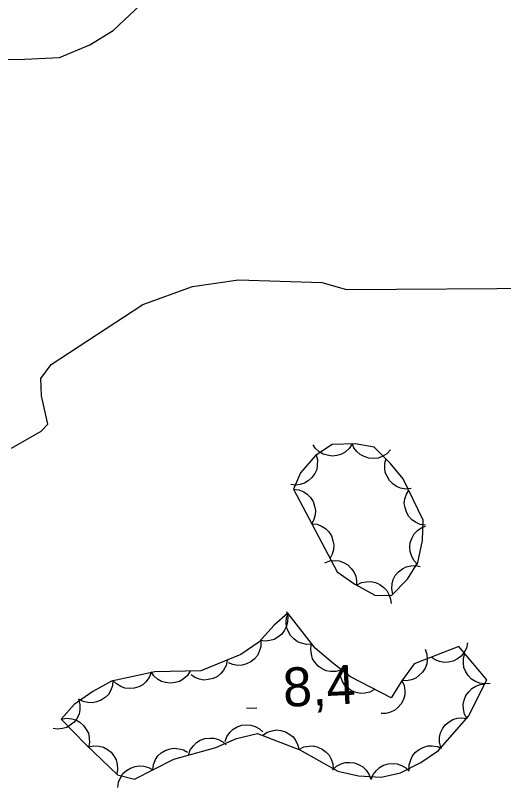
# Model space of a CAD drawing. Extents: x 336540 to 340074, y 5572036 to 5573747.
# Drawn here: x 337151.7 to 337189.3, y 5573239.4 to 5573298.8 of the extents above; entities that cross this region are included whole.
import ezdxf

# ---------------------------------------------------------------- set-up
doc = ezdxf.new("R2010")
doc.units = 0
for name, color, linetype in [('Niveau 2', 7, 'Continuous'), ('Niveau 3', 7, 'Continuous'), ('Niveau 44', 7, 'Continuous')]:
    doc.layers.add(name, color=color, linetype=linetype)

msp = doc.modelspace()

# ---------------------------------------------------------------- linework, layer by layer
at = {"layer": 'Niveau 2'}
for points in [[(337091.09, 5573283.05), (337093.43, 5573283.52), (337098.24, 5573285.63), (337100.53, 5573287.28), (337103.17, 5573288.42), (337108.54, 5573289.23), (337110.89, 5573289.85), (337113.42, 5573289.98), (337121.91, 5573292.45), (337127.4, 5573294.78), (337131.75, 5573295.67), (337134.79, 5573295.67), (337137.84, 5573295.82), (337140.38, 5573295.45), (337151.9, 5573295.36), (337155.09, 5573295.51), (337157.44, 5573296.49), (337159.22, 5573297.6), (337161.33, 5573299.56)], [(337151.4, 5573265.47), (337153.7, 5573266.78), (337154.19, 5573267.31), (337153.72, 5573269.49), (337153.65, 5573270.83), (337154.46, 5573271.89), (337161.5, 5573276.51), (337165.32, 5573277.89), (337168.86, 5573278.42), (337175.27, 5573278.22), (337177.17, 5573277.66), (337192.58, 5573277.76)]]:
    msp.add_lwpolyline(points, dxfattribs=at)
at = {"layer": 'Niveau 3'}
msp.add_line((337169.47, 5573245.46), (337170.27, 5573245.5), dxfattribs=at)
at = {"layer": 'Niveau 44'}
for points in [[(337173.09, 5573262.3), (337176.46, 5573255.96), (337177.81, 5573255), (337179.36, 5573254.17), (337180.64, 5573254.14), (337181.86, 5573255.38), (337182.67, 5573256.66), (337183.03, 5573258.37), (337183.07, 5573259.93), (337181.54, 5573263.1), (337180.54, 5573264.3), (337179.31, 5573265.54), (337177.83, 5573265.79), (337176.08, 5573265.76), (337174.78, 5573264.9), (337173.64, 5573263.56), (337173.09, 5573262.3)], [(337177.6, 5573265.79), (337177.37, 5573265.44), (337177.06, 5573265.17), (337176.78, 5573265), (337176.44, 5573264.9), (337176.07, 5573264.86), (337175.69, 5573264.92), (337175.38, 5573265), (337175.08, 5573265.19), (337174.8, 5573265.44), (337174.6, 5573265.73)], [(337180.56, 5573265.33), (337180.27, 5573265.03), (337179.92, 5573264.83), (337179.61, 5573264.7), (337179.26, 5573264.67), (337178.89, 5573264.7), (337178.53, 5573264.83), (337178.23, 5573264.97), (337177.98, 5573265.21), (337177.75, 5573265.5), (337177.6, 5573265.83)], [(337174.83, 5573264.96), (337174.94, 5573264.56), (337174.93, 5573264.15), (337174.88, 5573263.82), (337174.73, 5573263.51), (337174.51, 5573263.2), (337174.22, 5573262.96), (337173.95, 5573262.78), (337173.61, 5573262.68), (337173.24, 5573262.63), (337172.89, 5573262.67)], [(337182.15, 5573262.36), (337181.74, 5573262.32), (337181.34, 5573262.4), (337181.03, 5573262.51), (337180.74, 5573262.71), (337180.48, 5573262.97), (337180.29, 5573263.31), (337180.15, 5573263.6), (337180.11, 5573263.95), (337180.13, 5573264.32), (337180.23, 5573264.67)], [(337173.09, 5573262.3), (337173.51, 5573262.26), (337173.88, 5573262.1), (337174.16, 5573261.93), (337174.4, 5573261.67), (337174.6, 5573261.36), (337174.72, 5573261), (337174.79, 5573260.68), (337174.76, 5573260.33), (337174.67, 5573259.97), (337174.5, 5573259.65)], [(337183.26, 5573259.54), (337182.85, 5573259.6), (337182.48, 5573259.77), (337182.2, 5573259.95), (337181.97, 5573260.22), (337181.78, 5573260.53), (337181.68, 5573260.9), (337181.62, 5573261.22), (337181.67, 5573261.57), (337181.78, 5573261.93), (337181.96, 5573262.24)], [(337174.5, 5573259.65), (337174.91, 5573259.61), (337175.29, 5573259.45), (337175.57, 5573259.28), (337175.81, 5573259.02), (337176.01, 5573258.71), (337176.13, 5573258.35), (337176.2, 5573258.03), (337176.17, 5573257.68), (337176.07, 5573257.32), (337175.91, 5573257)], [(337182.64, 5573256.53), (337182.35, 5573256.83), (337182.17, 5573257.2), (337182.06, 5573257.51), (337182.04, 5573257.86), (337182.08, 5573258.22), (337182.22, 5573258.58), (337182.38, 5573258.87), (337182.63, 5573259.12), (337182.93, 5573259.33), (337183.26, 5573259.47)], [(337175.5, 5573256.64), (337175.89, 5573256.79), (337176.3, 5573256.82), (337176.62, 5573256.79), (337176.95, 5573256.67), (337177.27, 5573256.48), (337177.54, 5573256.21), (337177.75, 5573255.96), (337177.88, 5573255.63), (337177.95, 5573255.27), (337177.94, 5573254.91)], [(337180.73, 5573254.23), (337180.65, 5573254.64), (337180.68, 5573255.04), (337180.76, 5573255.36), (337180.93, 5573255.67), (337181.17, 5573255.96), (337181.48, 5573256.18), (337181.76, 5573256.34), (337182.11, 5573256.42), (337182.48, 5573256.43), (337182.83, 5573256.37)], [(337177.95, 5573254.92), (337178.32, 5573255.12), (337178.72, 5573255.19), (337179.05, 5573255.21), (337179.4, 5573255.13), (337179.73, 5573254.99), (337180.04, 5573254.75), (337180.27, 5573254.53), (337180.44, 5573254.22), (337180.56, 5573253.86), (337180.6, 5573253.51)], [(337155.23, 5573244.62), (337157.13, 5573242.67), (337159.57, 5573240.35), (337160.87, 5573240.01), (337163.88, 5573241.54), (337167.12, 5573242.43), (337168.72, 5573243.13), (337170.32, 5573243.53), (337173.59, 5573242.25), (337176.51, 5573240.62), (337178.1, 5573240.26), (337179.85, 5573240.15), (337181.34, 5573240.48), (337182.88, 5573241.3), (337184.24, 5573242.22), (337186.57, 5573244.86), (337187.98, 5573247.65), (337185.81, 5573250.22), (337182.39, 5573248.88), (337181.42, 5573247.56), (337180.6, 5573246.25), (337177.47, 5573247.87), (337176.1, 5573248.95), (337174.76, 5573250.08), (337172.67, 5573252.77), (337171.6, 5573251.85), (337170.43, 5573250.54), (337169.04, 5573249.59), (337165.98, 5573248.33), (337162.42, 5573248.26), (337159.11, 5573247.55), (337157.67, 5573246.75), (337156.22, 5573245.76), (337155.23, 5573244.62)], [(337172.55, 5573252.91), (337172.65, 5573252.51), (337172.63, 5573252.1), (337172.57, 5573251.78), (337172.41, 5573251.46), (337172.19, 5573251.17), (337171.89, 5573250.93), (337171.62, 5573250.75), (337171.28, 5573250.66), (337170.91, 5573250.63), (337170.55, 5573250.67)], [(337174.52, 5573250.39), (337174.1, 5573250.36), (337173.71, 5573250.46), (337173.4, 5573250.57), (337173.12, 5573250.79), (337172.87, 5573251.06), (337172.69, 5573251.39), (337172.56, 5573251.7), (337172.53, 5573252.05), (337172.57, 5573252.42), (337172.68, 5573252.76)], [(337170.58, 5573250.64), (337170.58, 5573250.22), (337170.46, 5573249.83), (337170.33, 5573249.53), (337170.1, 5573249.27), (337169.81, 5573249.03), (337169.47, 5573248.87), (337169.16, 5573248.77), (337168.8, 5573248.76), (337168.44, 5573248.82), (337168.1, 5573248.95)], [(337176.75, 5573248.4), (337176.35, 5573248.29), (337175.94, 5573248.29), (337175.62, 5573248.34), (337175.3, 5573248.49), (337175, 5573248.71), (337174.75, 5573249), (337174.57, 5573249.27), (337174.47, 5573249.61), (337174.42, 5573249.98), (337174.46, 5573250.33)], [(337186.49, 5573250.49), (337186.4, 5573250.08), (337186.2, 5573249.72), (337186, 5573249.46), (337185.71, 5573249.25), (337185.38, 5573249.09), (337185.01, 5573249.01), (337184.68, 5573248.98), (337184.34, 5573249.05), (337183.99, 5573249.19), (337183.69, 5573249.39)], [(337183.22, 5573250.01), (337183.36, 5573249.62), (337183.38, 5573249.21), (337183.35, 5573248.88), (337183.22, 5573248.55), (337183.03, 5573248.24), (337182.75, 5573247.97), (337182.5, 5573247.77), (337182.17, 5573247.65), (337181.8, 5573247.58), (337181.44, 5573247.59)], [(337188.22, 5573247.37), (337187.8, 5573247.33), (337187.4, 5573247.4), (337187.09, 5573247.51), (337186.8, 5573247.71), (337186.54, 5573247.97), (337186.34, 5573248.3), (337186.21, 5573248.6), (337186.17, 5573248.95), (337186.18, 5573249.32), (337186.28, 5573249.66)], [(337167.99, 5573249.16), (337167.91, 5573248.75), (337167.71, 5573248.39), (337167.52, 5573248.13), (337167.24, 5573247.91), (337166.91, 5573247.74), (337166.53, 5573247.66), (337166.21, 5573247.62), (337165.86, 5573247.69), (337165.52, 5573247.82), (337165.22, 5573248.02)], [(337162.16, 5573248.2), (337162, 5573247.82), (337161.75, 5573247.5), (337161.51, 5573247.27), (337161.2, 5573247.11), (337160.84, 5573247.01), (337160.46, 5573246.99), (337160.13, 5573247.01), (337159.81, 5573247.14), (337159.49, 5573247.33), (337159.23, 5573247.58)], [(337165.15, 5573248.31), (337164.93, 5573247.96), (337164.62, 5573247.7), (337164.34, 5573247.52), (337164, 5573247.43), (337163.63, 5573247.39), (337163.25, 5573247.44), (337162.94, 5573247.53), (337162.64, 5573247.71), (337162.36, 5573247.96), (337162.15, 5573248.25)], [(337179.34, 5573246.9), (337178.98, 5573246.7), (337178.58, 5573246.62), (337178.25, 5573246.6), (337177.91, 5573246.67), (337177.56, 5573246.81), (337177.26, 5573247.04), (337177.02, 5573247.27), (337176.85, 5573247.57), (337176.72, 5573247.92), (337176.68, 5573248.28)], [(337159.21, 5573247.61), (337159.18, 5573247.19), (337159.03, 5573246.81), (337158.86, 5573246.53), (337158.61, 5573246.28), (337158.3, 5573246.08), (337157.94, 5573245.95), (337157.62, 5573245.87), (337157.27, 5573245.9), (337156.91, 5573245.99), (337156.59, 5573246.15)], [(337181.44, 5573247.59), (337181.61, 5573247.21), (337181.66, 5573246.81), (337181.66, 5573246.48), (337181.55, 5573246.14), (337181.38, 5573245.81), (337181.13, 5573245.53), (337180.89, 5573245.31), (337180.57, 5573245.16), (337180.21, 5573245.06), (337179.85, 5573245.05)], [(337186.46, 5573244.65), (337186.26, 5573245.01), (337186.17, 5573245.41), (337186.15, 5573245.74), (337186.22, 5573246.08), (337186.36, 5573246.43), (337186.58, 5573246.73), (337186.81, 5573246.97), (337187.11, 5573247.15), (337187.46, 5573247.28), (337187.82, 5573247.32)], [(337156.56, 5573246.15), (337156.67, 5573245.75), (337156.66, 5573245.34), (337156.6, 5573245.02), (337156.45, 5573244.7), (337156.23, 5573244.4), (337155.93, 5573244.16), (337155.66, 5573243.98), (337155.32, 5573243.89), (337154.95, 5573243.85), (337154.6, 5573243.89)], [(337155.23, 5573244.62), (337155.64, 5573244.69), (337156.04, 5573244.65), (337156.36, 5573244.56), (337156.67, 5573244.38), (337156.95, 5573244.14), (337157.16, 5573243.83), (337157.32, 5573243.54), (337157.39, 5573243.19), (337157.4, 5573242.82), (337157.32, 5573242.47)], [(337184.43, 5573242.43), (337184.32, 5573242.84), (337184.34, 5573243.24), (337184.4, 5573243.57), (337184.55, 5573243.88), (337184.77, 5573244.18), (337185.07, 5573244.42), (337185.35, 5573244.6), (337185.69, 5573244.69), (337186.05, 5573244.73), (337186.41, 5573244.68)], [(337167.83, 5573242.91), (337167.97, 5573243.3), (337168.22, 5573243.63), (337168.45, 5573243.86), (337168.76, 5573244.03), (337169.11, 5573244.15), (337169.49, 5573244.18), (337169.82, 5573244.17), (337170.15, 5573244.05), (337170.47, 5573243.88), (337170.74, 5573243.64)], [(337170.72, 5573243.37), (337171.07, 5573243.61), (337171.46, 5573243.73), (337171.78, 5573243.79), (337172.13, 5573243.75), (337172.49, 5573243.64), (337172.81, 5573243.45), (337173.07, 5573243.25), (337173.28, 5573242.96), (337173.44, 5573242.63), (337173.52, 5573242.28)], [(337165.03, 5573241.86), (337165.16, 5573242.25), (337165.4, 5573242.58), (337165.63, 5573242.82), (337165.93, 5573243), (337166.28, 5573243.13), (337166.66, 5573243.17), (337166.98, 5573243.16), (337167.32, 5573243.05), (337167.65, 5573242.88), (337167.92, 5573242.65)], [(337157.33, 5573242.48), (337157.74, 5573242.57), (337158.14, 5573242.54), (337158.47, 5573242.47), (337158.78, 5573242.3), (337159.06, 5573242.07), (337159.29, 5573241.76), (337159.46, 5573241.48), (337159.54, 5573241.14), (337159.56, 5573240.77), (337159.51, 5573240.41)], [(337173.52, 5573242.29), (337173.9, 5573242.48), (337174.3, 5573242.55), (337174.63, 5573242.56), (337174.97, 5573242.47), (337175.3, 5573242.32), (337175.6, 5573242.08), (337175.83, 5573241.85), (337176, 5573241.54), (337176.11, 5573241.18), (337176.14, 5573240.83)], [(337181.99, 5573240.7), (337181.99, 5573241.11), (337182.11, 5573241.5), (337182.24, 5573241.8), (337182.48, 5573242.07), (337182.76, 5573242.3), (337183.11, 5573242.46), (337183.42, 5573242.56), (337183.77, 5573242.57), (337184.14, 5573242.51), (337184.47, 5573242.38)], [(337162.27, 5573240.72), (337162.32, 5573241.13), (337162.48, 5573241.51), (337162.66, 5573241.79), (337162.92, 5573242.02), (337163.23, 5573242.22), (337163.6, 5573242.33), (337163.92, 5573242.39), (337164.27, 5573242.35), (337164.63, 5573242.25), (337164.94, 5573242.08)], [(337159.59, 5573239.36), (337159.64, 5573239.78), (337159.81, 5573240.15), (337159.98, 5573240.43), (337160.25, 5573240.66), (337160.56, 5573240.86), (337160.93, 5573240.97), (337161.24, 5573241.04), (337161.59, 5573241), (337161.95, 5573240.89), (337162.27, 5573240.72)], [(337176.1, 5573240.71), (337176.4, 5573241), (337176.77, 5573241.18), (337177.08, 5573241.28), (337177.43, 5573241.3), (337177.8, 5573241.25), (337178.15, 5573241.1), (337178.44, 5573240.95), (337178.68, 5573240.69), (337178.89, 5573240.39), (337179.03, 5573240.05)], [(337179.06, 5573239.98), (337179.22, 5573240.36), (337179.47, 5573240.68), (337179.71, 5573240.91), (337180.02, 5573241.07), (337180.37, 5573241.18), (337180.76, 5573241.2), (337181.08, 5573241.18), (337181.41, 5573241.06), (337181.73, 5573240.87), (337181.99, 5573240.62)]]:
    msp.add_lwpolyline(points, dxfattribs=at)

# ---------------------------------------------------------------- texts
at = {"layer": 'Niveau 3'}
msp.add_text('8,4    ', height=3, rotation=2.7712, dxfattribs=at).set_placement((337172.35, 5573245.56))

doc.saveas('drawing.dxf')
